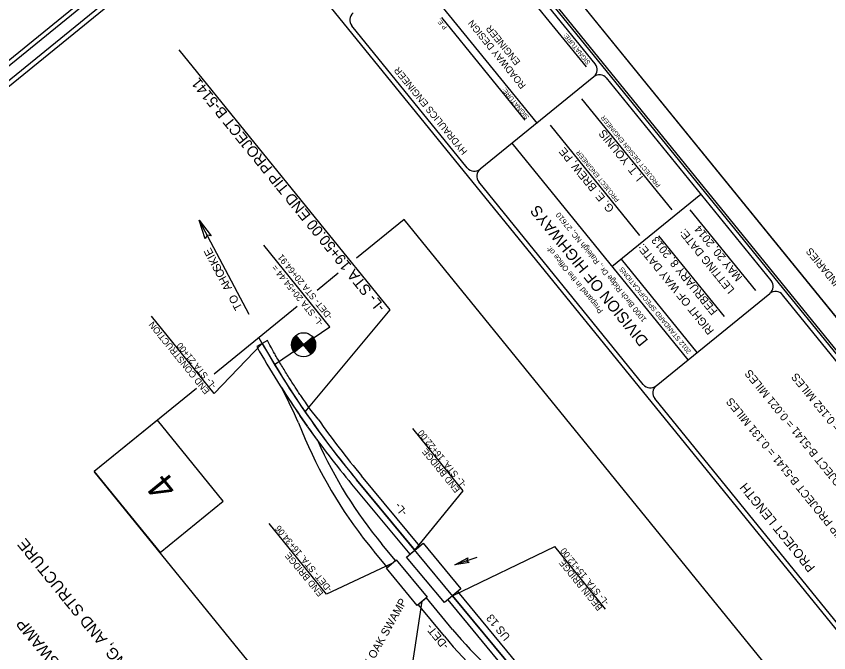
# Model space of a CAD drawing. Extents: x 2596486 to 2602076, y 851390 to 856110.
# Drawn here: x 2597258 to 2598768, y 853129 to 854310 of the extents above; entities that cross this region are included whole.
import ezdxf

# ---------------------------------------------------------------- set-up
doc = ezdxf.new("R2010")
doc.units = 0
for name, color, linetype in [('Old_Level_1', 7, 'Continuous'), ('Old_Level_23', 7, 'Continuous'), ('Prop Dimension Text', 7, 'Continuous'), ('Prop Horizontal Alignment', 7, 'Continuous'), ('Prop Roadway Bridge', 7, 'Continuous'), ('Prop Shade Light', 7, 'Continuous'), ('Prop Shade Medium', 7, 'Continuous'), ('Prop Terminator CELL', 7, 'Continuous'), ('Sheet Cutting Line CELL', 7, 'Continuous'), ('Sheet Data Field CELL', 7, 'Continuous'), ('Sheet Data Text CELL', 7, 'Continuous'), ('Sheet Plot Border Inside CELL', 7, 'Continuous'), ('Sheet Plot Border Outside CELL', 7, 'Continuous'), ('Sheet Title CELL', 7, 'Continuous'), ('Typical Grade Point Symbol CELL', 7, 'Continuous')]:
    doc.layers.add(name, color=color, linetype=linetype)

msp = doc.modelspace()

# ---------------------------------------------------------------- linework, layer by layer
at = {"layer": 'Old_Level_1'}
for p, q in [((2597691.4, 853756.5), (2597598.2, 853931.9)), ((2597979.3, 853933.2), (2597890.8, 853861.2)), ((2598676.9, 853075), (2597979.3, 853933.2)), ((2597856.5, 853833.3), (2597817.3, 853801.5)), ((2597780.3, 853771.4), (2597626, 853646)), ((2597626.1, 853610.2), (2597509.7, 853753.5)), ((2597593.1, 853619.2), (2597403.5, 853465.1)), ((2598101, 852606.9), (2597403.5, 853465.1)), ((2597999.1, 853319), (2598089, 853429.4)), ((2598069.3, 853234.4), (2598259.2, 853325.6)), ((2598114.4, 853305.4), (2598073.1, 853292.1))]:
    msp.add_line(p, q, dxfattribs=at)
for points in [[(2597795.1, 853575.8), (2597953.2, 853765.4), (2597561, 854248)], [(2597738.5, 853663.5), (2597841, 853734), (2597718.2, 853885.1)]]:
    msp.add_lwpolyline(points, dxfattribs=at)
msp.add_lwpolyline([(2597403.5, 853465.1), (2597525.9, 853314.5), (2597643.1, 853409.8), (2597520.7, 853560.4)], close=True, dxfattribs=at)
at = {"layer": 'Prop Dimension Text'}
for p, q in [((2597715.4, 853702.8), (2597626.1, 853610.2)), ((2598089, 853429.4), (2597995, 853545)), ((2598353.4, 853209.6), (2598259.2, 853325.6))]:
    msp.add_line(p, q, dxfattribs=at)
for points in [[(2597955.3, 853293.5), (2597835, 853237.3), (2597728.2, 853368.7)], [(2598106.5, 852968.5), (2597994.5, 853106.3), (2598012.8, 853224.2)]]:
    msp.add_lwpolyline(points, dxfattribs=at)
at = {"layer": 'Prop Horizontal Alignment'}
msp.add_line((2598276.5, 852984.9), (2597890.8, 853449.4), dxfattribs=at)
msp.add_arc((2599247.1, 854575.6), 1762.9, 209.2814, 219.7067, dxfattribs=at)
at = {"layer": 'Prop Roadway Bridge'}
msp.add_lwpolyline([(2598053.9, 853221.6), (2597983.7, 853306.3), (2598014.5, 853331.8), (2598084.7, 853247.1)], close=True, dxfattribs=at)
at = {"layer": 'Prop Shade Light'}
for p, q in [((2597715.4, 853702.8), (2597705.3, 853697)), ((2597725.1, 853708.4), (2597715.4, 853702.8)), ((2597819.2, 853562.3), (2597803.9, 853581.8)), ((2597785.5, 853569.2), (2597799.6, 853548.4)), ((2597799.6, 853548.4), (2597785.5, 853569.2)), ((2597782.6, 853555.5), (2597795.5, 853525.3)), ((2597999.1, 853319), (2597890.8, 853449.4)), ((2597890.8, 853449.4), (2597999.1, 853319)), ((2598008.3, 853326.7), (2597900.1, 853457)), ((2597881.6, 853441.7), (2597989.8, 853311.4)), ((2597963, 853299.9), (2597937.7, 853330.3)), ((2597999.8, 853319.6), (2598008.3, 853326.7)), ((2597922.3, 853317.5), (2597947.6, 853287.1)), ((2597989.8, 853311.4), (2597999.1, 853319)), ((2597999.1, 853319), (2597999.8, 853319.6)), ((2597947.6, 853287.1), (2597963, 853299.9)), ((2598069.3, 853234.4), (2598060.1, 853226.7)), ((2598078.6, 853242.1), (2598069.3, 853234.4)), ((2598276.5, 852984.9), (2598069.3, 853234.4)), ((2598069.3, 853234.4), (2598276.5, 852984.9)), ((2598285.7, 852992.6), (2598078.6, 853242.1)), ((2598020.5, 853230.6), (2598005.1, 853217.8)), ((2598005.1, 853217.8), (2598053.8, 853159.2)), ((2598069.2, 853172), (2598020.5, 853230.6)), ((2598060.1, 853226.7), (2598267.3, 852977.3))]:
    msp.add_line(p, q, dxfattribs=at)
for centre, radius, start, end in [((2599247.1, 854575.6), 1762.9, 209.6754, 219.7067), ((2599247.1, 854575.6), 1762.9, 209.6754, 219.7067), ((2599247.1, 854575.6), 1774.6, 209.6754, 214.5504), ((2599247.1, 854575.6), 1774.6, 212.5461, 214.5504), ((2597025.6, 853232.6), 823, 23.1003, 28.1578), ((2599247.1, 854575.6), 1774.9, 215.3629, 219.7067), ((2599247.1, 854575.6), 1774.9, 215.3629, 216.4145), ((2599247.1, 854575.6), 1750.9, 215.3629, 219.7067), ((2598570.9, 853856.1), 843, 203.1003, 219.7067), ((2598570.9, 853856.1), 823, 203.949, 219.7067), ((2598702.4, 853697.7), 823, 219.7067, 233.4707), ((2598702.4, 853697.7), 843, 219.7067, 233.4707)]:
    msp.add_arc(centre, radius, start, end, dxfattribs=at)
msp.add_open_spline([(2597803.9, 853581.8), (2597798.6, 853589.3), (2597793.4, 853596.9), (2597788.2, 853604.5), (2597783, 853612.1), (2597777.9, 853619.8), (2597772.9, 853627.5), (2597760.5, 853646.9), (2597748.3, 853666.5), (2597737.1, 853686.7), (2597733.1, 853693.9), (2597729.1, 853701.1), (2597725.1, 853708.4)], degree=3, dxfattribs=at)
at = {"layer": 'Prop Shade Medium'}
for points in [[(2598053.9, 853221.6), (2597983.7, 853306.3), (2598014.5, 853331.8), (2598084.7, 853247.1)], [(2598022, 853231.9), (2598003.6, 853216.6), (2597946.1, 853285.8), (2597964.5, 853301.1)]]:
    msp.add_lwpolyline(points, close=True, dxfattribs=at)
at = {"layer": 'Prop Terminator CELL'}
for points in [[(2597609.6, 853897.2), (2597598.2, 853931.9), (2597620.8, 853902.9), (2597613, 853904)], [(2598100.2, 853296), (2598073.1, 853292.1), (2598097.4, 853305), (2598095.6, 853299.4)]]:
    msp.add_lwpolyline(points, close=True, dxfattribs=at)
at = {"layer": 'Sheet Cutting Line CELL'}
msp.add_line((2599742.7, 852569.6), (2597937, 854791.2), dxfattribs=at)
at = {"layer": 'Sheet Plot Border Inside CELL'}
msp.add_lwpolyline([(2599699.1, 852562.7), (2597912.3, 854761.2), (2596520.4, 853629.9), (2598307.2, 851431.4)], close=True, dxfattribs=at)
at = {"layer": 'Sheet Plot Border Outside CELL'}
msp.add_lwpolyline([(2596485.9, 853611.8), (2598291.5, 851390.2), (2599742.7, 852569.6), (2597937, 854791.2)], close=True, dxfattribs=at)
at = {"layer": 'Sheet Title CELL'}
for p, q in [((2599210.3, 852645.2), (2597687.7, 854518.5)), ((2598226.8, 854111.2), (2597990.2, 854402.3)), ((2598317.9, 854216.3), (2598166.2, 854403)), ((2598204, 854117.7), (2598049.4, 854308)), ((2598096.4, 854029.1), (2597882.2, 854292.7)), ((2598331.4, 854198.2), (2598120.3, 854026.7)), ((2598477, 853951), (2598309.5, 854157.1)), ((2598417.3, 853903.2), (2598251, 854107.9)), ((2598179.4, 854074.7), (2598506.4, 853672.3)), ((2598423.4, 853626.8), (2598117.8, 854002.7)), ((2598365.3, 853845.8), (2598530.6, 853980.1)), ((2598510.1, 853951.2), (2598632.1, 853801.2)), ((2598451.7, 853902.9), (2598573.7, 853752.8)), ((2598382.2, 853859.5), (2598523.2, 853686)), ((2598512.7, 853827.8), (2598512.7, 853827.8)), ((2598422.8, 853809.5), (2598422.8, 853809.5)), ((2598447.3, 853624.3), (2598658.4, 853795.9)), ((2598852.3, 853099.1), (2598444.9, 853600.4))]:
    msp.add_line(p, q, dxfattribs=at)
for points in [[(2597909.1, 854731.3), (2596550.3, 853626.9)], [(2599519.9, 852776.4), (2597933, 854728.8)], [(2597663.8, 854521), (2596562.3, 853625.7)], [(2598333.9, 854222.1), (2598119.7, 854485.7)], [(2598660.9, 853819.8), (2598355.3, 854195.8)], [(2599089.8, 853292.1), (2598682.3, 853793.4)]]:
    msp.add_lwpolyline(points, dxfattribs=at)
for centre, start, end in [((2597895.4, 854303.4), 129.1028, 219.1028), ((2598320.7, 854211.4), 309.1028, 39.1028), ((2598342.1, 854185), 39.1028, 129.1028), ((2598109.6, 854039.9), 219.1028, 309.1028), ((2598131, 854013.5), 129.1028, 219.1028), ((2598647.7, 853809), 309.1028, 39.1028), ((2598669.2, 853782.7), 39.1028, 129.1028), ((2598436.6, 853637.5), 219.1028, 309.1028), ((2598458.1, 853611.1), 129.1028, 219.1028)]:
    msp.add_arc(centre, 17, start, end, dxfattribs=at)
at = {"layer": 'Typical Grade Point Symbol CELL'}
for p, q in [((2597778.1, 853717.9), (2597792.2, 853700.5)), ((2597809.6, 853714.6), (2597792.2, 853700.5)), ((2597792.2, 853700.5), (2597809.6, 853714.6)), ((2597792.2, 853700.5), (2597774.9, 853686.4)), ((2597806.4, 853683.2), (2597792.2, 853700.5))]:
    msp.add_line(p, q, dxfattribs=at)
for points in [[(2597770.5, 853705.6), (2597781.1, 853714.2)], [(2597770.6, 853706.3), (2597780.8, 853714.6)], [(2597770.9, 853707.1), (2597780.5, 853714.9)], [(2597771.1, 853707.9), (2597780.3, 853715.3)], [(2597771.4, 853708.7), (2597780, 853715.6)], [(2597771.8, 853709.5), (2597779.7, 853716)], [(2597772.2, 853710.5), (2597779.4, 853716.3)], [(2597772.7, 853711.5), (2597779.1, 853716.7)], [(2597773.4, 853712.6), (2597778.9, 853717)], [(2597774.3, 853713.9), (2597778.6, 853717.4)], [(2597775.8, 853715.7), (2597778.3, 853717.7)], [(2597792.5, 853700.3), (2597809.8, 853714.4), (2597809.8, 853714.4)], [(2597769.9, 853702.3), (2597782.5, 853712.5)], [(2597769.9, 853701.7), (2597782.8, 853712.2)], [(2597769.9, 853701.1), (2597783.1, 853711.8)], [(2597769.9, 853700.5), (2597783.4, 853711.5)], [(2597769.9, 853699.9), (2597783.7, 853711.1)], [(2597769.9, 853699.4), (2597783.9, 853710.8)], [(2597769.9, 853698.8), (2597784.2, 853710.4)], [(2597770, 853702.9), (2597782.2, 853712.9)], [(2597770, 853698.3), (2597784.5, 853710.1)], [(2597770, 853697.7), (2597784.8, 853709.7)], [(2597770.1, 853703.5), (2597782, 853713.2)], [(2597770.1, 853697.2), (2597785.1, 853709.4)], [(2597770.2, 853704.2), (2597781.7, 853713.6)], [(2597770.2, 853696.7), (2597785.3, 853709)], [(2597770.3, 853704.9), (2597781.4, 853713.9)], [(2597770.3, 853696.2), (2597785.6, 853708.7)], [(2597770.4, 853695.7), (2597785.9, 853708.3)], [(2597770.5, 853695.3), (2597786.2, 853708)], [(2597770.7, 853694.8), (2597786.5, 853707.6)], [(2597770.8, 853694.3), (2597786.8, 853707.3)], [(2597770.9, 853693.8), (2597787, 853707)], [(2597771, 853693.4), (2597787.3, 853706.6)], [(2597771.2, 853692.9), (2597787.6, 853706.3)], [(2597771.4, 853692.5), (2597787.9, 853705.9)], [(2597771.5, 853692), (2597788.2, 853705.6)], [(2597771.7, 853691.6), (2597788.5, 853705.2)], [(2597771.9, 853691.2), (2597788.7, 853704.9)], [(2597772.1, 853690.8), (2597789, 853704.5)], [(2597772.3, 853690.4), (2597789.3, 853704.2)], [(2597772.5, 853690), (2597789.6, 853703.8)], [(2597772.7, 853689.6), (2597789.9, 853703.5)], [(2597773, 853689.2), (2597790.1, 853703.1)], [(2597773.2, 853688.8), (2597790.4, 853702.8)], [(2597773.5, 853688.4), (2597790.7, 853702.4)], [(2597773.7, 853688), (2597791, 853702.1)], [(2597773.9, 853687.7), (2597791.3, 853701.7)], [(2597774.2, 853687.3), (2597791.6, 853701.4)], [(2597774.5, 853686.9), (2597791.8, 853701)], [(2597774.8, 853686.6), (2597774.8, 853686.6), (2597792.1, 853700.7)], [(2597792.7, 853699.9), (2597810.1, 853714)], [(2597793, 853699.6), (2597810.4, 853713.7)], [(2597793.3, 853699.2), (2597810.6, 853713.3)], [(2597793.6, 853698.9), (2597810.9, 853712.9)], [(2597793.9, 853698.5), (2597811.1, 853712.6)], [(2597794.2, 853698.2), (2597811.4, 853712.2)], [(2597794.4, 853697.8), (2597811.6, 853711.8)], [(2597794.7, 853697.5), (2597811.8, 853711.4)], [(2597795, 853697.2), (2597812, 853711)], [(2597795.3, 853696.8), (2597812.2, 853710.6)], [(2597795.6, 853696.5), (2597812.4, 853710.2)], [(2597795.9, 853696.1), (2597812.6, 853709.8)], [(2597796.1, 853695.8), (2597812.8, 853709.3)], [(2597796.4, 853695.4), (2597813, 853708.9)], [(2597796.7, 853695.1), (2597813.2, 853708.5)], [(2597797, 853694.7), (2597813.3, 853708)], [(2597797.3, 853694.4), (2597813.5, 853707.6)], [(2597797.5, 853694), (2597813.6, 853707.1)], [(2597797.8, 853693.7), (2597813.8, 853706.6)], [(2597798.1, 853693.3), (2597813.9, 853706.2)], [(2597798.4, 853693), (2597814, 853705.7)], [(2597798.7, 853692.6), (2597814.2, 853705.2)], [(2597799, 853692.3), (2597814.2, 853704.7)], [(2597799.2, 853691.9), (2597814.3, 853704.2)], [(2597799.5, 853691.6), (2597814.4, 853703.7)], [(2597799.8, 853691.2), (2597814.5, 853703.2)], [(2597800.1, 853690.9), (2597814.5, 853702.6)], [(2597800.4, 853690.6), (2597814.6, 853702.1)], [(2597800.7, 853690.2), (2597814.6, 853701.6)], [(2597800.9, 853689.9), (2597814.6, 853701)], [(2597801.2, 853689.5), (2597814.6, 853700.4)], [(2597801.5, 853689.2), (2597814.6, 853699.8)], [(2597801.8, 853688.8), (2597814.6, 853699.2)], [(2597802.1, 853688.5), (2597814.6, 853698.6)], [(2597802.3, 853688.1), (2597814.5, 853698)], [(2597802.6, 853687.8), (2597814.4, 853697.3)], [(2597802.9, 853687.4), (2597814.3, 853696.7)], [(2597803.2, 853687.1), (2597814.2, 853696)], [(2597803.5, 853686.7), (2597814, 853695.3)], [(2597803.8, 853686.4), (2597813.8, 853694.6)], [(2597804, 853686), (2597813.6, 853693.8)], [(2597804.3, 853685.7), (2597813.4, 853693)], [(2597804.6, 853685.3), (2597813, 853692.2)], [(2597804.9, 853685), (2597812.6, 853691.3)], [(2597805.2, 853684.6), (2597812.2, 853690.4)], [(2597805.5, 853684.3), (2597811.7, 853689.3)], [(2597805.7, 853684), (2597810.9, 853688.2)], [(2597806, 853683.6), (2597810, 853686.8)], [(2597806.3, 853683.3), (2597808.2, 853684.8)]]:
    msp.add_lwpolyline(points, dxfattribs=at)
msp.add_circle((2597792.3, 853700.5), 22.4, dxfattribs=at)
for start, end in [(129.0933, 219.0933), (309.0933, 39.0933)]:
    msp.add_arc((2597792.3, 853700.5), 22.4, start, end, dxfattribs=at)

# ---------------------------------------------------------------- texts
at = {"layer": 'Old_Level_1'}
for s, height, rotation, p in [('-L- STA 19+50.00 END TIP PROJECT B-5141', 20, 129.1027, (2597945.1, 853770.8)), ('E', 15, 118.0002, (2597625.6, 853870)), ('I', 15, 118.0002, (2597628.4, 853864.8)), ('-DET- STA 20+64.91', 12, 129.1027, (2597847, 853753.3)), ('K', 15, 118.0002, (2597634.6, 853853.1)), ('S', 15, 118.0002, (2597641, 853841)), ('O', 15, 118.0002, (2597646.9, 853830)), ('-L- STA 20+54.44 =', 12, 129.1027, (2597830, 853741)), ('H', 15, 118.0002, (2597653.9, 853816.8)), ('A', 15, 118.0002, (2597659.7, 853805.8)), ('O', 15, 118.0002, (2597672.7, 853781.5)), ('T', 15, 118.0002, (2597679.1, 853769.4)), ('END CONSTRUCTION', 12, 129.1027, (2597618.6, 853614.7)), ('-L- STA 21+00', 12, 129.1027, (2597630.8, 853624.7)), ('-L- STA. 16+22.00', 12, 129.1027, (2598095.8, 853441.6)), ('END BRIDGE', 12, 129.1027, (2598083.6, 853431.7)), ('4', 51, 129.1028, (2597560.9, 853436.6)), ('-L-', 15, 129.1028, (2597985.9, 853389.8)), ('-L- STA. 15+12.00', 12, 129.1027, (2598360.5, 853222.6)), ('BEGIN BRIDGE', 12, 129.1027, (2598348.3, 853212.7)), ('WHITE OAK SWAMP', 15, 60.8082, (2597890.1, 853054.9)), ('US 13', 15, 129.1028, (2598177.3, 853158.6)), ('-DET-', 15, 129.1028, (2598063.2, 853142.1))]:
    msp.add_text(s, height=height, rotation=rotation, dxfattribs=at).set_placement(p)
at = {"layer": 'Old_Level_23'}
msp.add_text('THIS PROJECT IS NOT WITHIN ANY MUNICIPAL BOUNDARIES ', height=13.5, rotation=129.1028, dxfattribs=at).set_placement((2599072.2, 853467))
at = {"layer": 'Sheet Data Field CELL'}
for s, height, p in [('I. T. YOUNIS', 14.875, (2598424.1, 854011.4)), ('G. E. BREW, PE', 14.875, (2598370.3, 853953.5)), ('MAY 20, 2014', 14.875, (2598608.3, 853825.8)), ('FEBRUARY 8, 2013', 14.875, (2598562.4, 853763.2)), ('GRADING, DRAINAGE, PAVING, AND STRUCTURE', 21.25, (2597703.6, 852816.1)), ('BRIDGE 53 ON US 13 OVER WHITE OAK SWAMP ', 21.25, (2597687.3, 852685.1))]:
    msp.add_text(s, height=height, rotation=129.1028, dxfattribs=at).set_placement(p)
at = {"layer": 'Sheet Data Text CELL'}
for s, p in [('-DET- STA. 16+34.06', (2597846.3, 853247.3)), (' END BRIDGE', (2597832.5, 853235.8))]:
    msp.add_text(s, height=12, rotation=129.7066, dxfattribs=at).set_placement(p)
at = {"layer": 'Sheet Title CELL'}
for s, height, p in [('P.E.', 8.5, (2598059.5, 854290)), ('ROADWAY DESIGN', 12.749, (2598206.3, 854182.2)), ('ENGINEER', 12.75, (2598195.9, 854226)), ('SIGNATURE:', 8.5, (2598325.8, 854224.7)), (' HYDRAULICS ENGINEER', 12.75, (2598100.4, 854055.9)), ('SIGNATURE:', 8.5, (2598211.8, 854123.4)), ('PROJECT DESIGN ENGINEER', 8.499, (2598456.2, 853996.9)), ('PROJECT ENGINEER', 8.499, (2598379.6, 853969.7)), ('DIVISION OF HIGHWAYS', 20.718, (2598433.6, 853708.4)), ('1000 Birch Ridge Dr., Raleigh NC, 27610', 10.2, (2598430.2, 853747.6)), ('LETTING DATE:', 14.875, (2598593.8, 853802.9)), ('Prepared in the Office of:', 10.199, (2598349.3, 853763.7)), ('RIGHT OF WAY DATE: ', 14.875, (2598555.7, 853726.7)), ('2012 STANDARD SPECIFICATIONS', 8.84, (2598512.9, 853688.2)), ('LENGTH OF STRUCTURE TIP PROJECT B-5141 = 0.021 MILES', 14.826, (2598989.3, 853204)), ('TOTAL LENGTH OF TIP PROJECT B-5141 = 0.152 MILES', 14.826, (2599039, 853242.9)), ('LENGTH OF ROADWAY TIP PROJECT B-5141 = 0.131 MILES', 14.826, (2598942.3, 853167.1)), ('PROJECT LENGTH', 16.999, (2598743.7, 853287))]:
    msp.add_text(s, height=height, rotation=129.1028, dxfattribs=at).set_placement(p)

doc.saveas('drawing.dxf')
